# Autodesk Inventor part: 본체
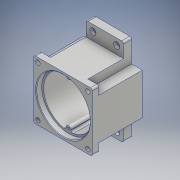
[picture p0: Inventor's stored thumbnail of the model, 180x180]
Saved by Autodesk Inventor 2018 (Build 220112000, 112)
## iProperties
Created: 2020-07
Part Number: 본체
Material: 알루미늄 6061
Document SubType Name: Modeling
Designer: Admin
Density: 2.7 g/cm^3
Appearance: 알루미늄 - 평지
Mass: 876.354 g
Surface Area: 793.925 cm^2
Volume: 324.576 cm^3
Author: Admin
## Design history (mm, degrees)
sketch "스케치1"
  geometry: L1 (65.8, 0)-(-65.8, 0) reference; L2 (0, -65.8)-(0, 65.8) reference; L3 (47, -47)-(-47, -47); L4 (-47, -47)-(-47, 47); L5 (-47, 47)-(47, 47); L6 (47, 47)-(47, -47); L7 (47, -47)-(-47, 47); L8 (-47, -47)-(47, 47); 1 further point
  constraints: 12 end point, 2 midpoint, 2 parallel, 1 horizontal, 1 perpendicular
  dimensions: "d0" = 94 distance of L4.end L5.end; "d1" = 94 distance of L3.end L4.end
extrude "돌출1" new body sketch "스케치1" distance "d2" = 10; taper "d3" = 0 deg
sketch "스케치2"
  geometry: L1 (-65.8, 0)-(65.8, 0) reference; L2 (0, 65.8)-(0, -65.8) reference; L3 (47, -33)-(-47, -33); L4 (-47, -33)-(-47, 33); L5 (-47, 33)-(47, 33); L6 (47, 33)-(47, -33); L7 (47, -33)-(-47, 33); L8 (-47, -33)-(47, 33); 1 further point
  constraints: 12 end point, 2 midpoint, 2 parallel, 1 horizontal, 1 perpendicular
  dimensions: "d4" = 94 distance of L4.end L5.end; "d5" = 66 distance of L3.end L4.end
extrude "돌출2" join sketch "스케치2" distance "d6" = 57; taper "d7" = 0 deg
sketch "스케치3"
  geometry: L1 (-47, -33)-(47, -33) reference; L2 (47, -33)-(47, 33) reference; L3 (47, 33)-(-47, 33) reference; L4 (-47, 33)-(-47, -33) reference; L5 (-65.8, 0)-(65.8, 0) reference; L6 (0, 98)-(0, -98) reference; L7 (30, -70)-(-30, -70); L8 (-30, -70)-(-30, 70); L9 (-30, 70)-(30, 70); L10 (30, 70)-(30, -70); L11 (30, -70)-(-30, 70); L12 (-30, -70)-(30, 70); L13 (-30, -70)-(30, -70); L14 (-30, 70)-(30, 70); L15 (47, -33)-(47, 33) reference; L16 (47, -33)-(47, 33); L17 (-47, -33)-(-47, 33); L18 (47, -33)-(-47, -33) reference; L19 (-47, -33)-(-30, -33); L20 (-30, -70)-(-30, -33); L21 (-47, 33)-(47, 33) reference; L22 (-47, 33)-(-30, 33); L23 (-30, 33)-(-30, 70); L24 (30, -70)-(30, -33); L25 (30, -33)-(47, -33); L26 (30, 33)-(47, 33); L27 (30, 33)-(30, 70); 1 further point
  constraints: 36 end point, 9 point on line, 7 collinear, 2 midpoint, 2 parallel, 1 horizontal, 1 perpendicular, 1 vertical
  dimensions: "d8" = 60 distance of L8.end L9.end; "d9" = 140 distance of L7.end L8.end
extrude "돌출3" join sketch "스케치3" distance "d10" = 13; taper "d11" = 0 deg
sketch "스케치4"
  geometry: L1 (-47, -33)-(-30, -33) reference; L2 (-30, -33)-(-30, -70) reference; L3 (-30, -70)-(30, -70) reference; L4 (30, -70)-(30, -33) reference; L5 (30, -33)-(47, -33) reference; L6 (47, -33)-(47, 33) reference; L7 (47, 33)-(30, 33) reference; L8 (30, 33)-(30, 70) reference; L9 (30, 70)-(-30, 70) reference; L10 (-30, 70)-(-30, 33) reference; L11 (-30, 33)-(-47, 33) reference; L12 (-47, 33)-(-47, -33) reference; L13 (-65.8, 0)-(65.8, 0) reference; L14 (0, 98)-(0, -98) reference; C1 r 27.5 at (-11, 0); 1 further point
  constraints: 1 centre point, 1 point on line
  dimensions: "d12" = 55 diameter of C1; "d13" = 11 distance of point (0, 0) C1.centre
extrude "돌출4" join sketch "스케치4" distance "d14" = 7; taper "d15" = 0 deg
sketch "스케치5"
  geometry: C1 r 27.5 at (0, 0) reference; C2 r 16 at (0, 0); 1 further point
  constraints: 1 centre point, 1 coincident
  dimensions: "d16" = 32 diameter of C2
extrude "돌출5" cut sketch "스케치5" distance "d17" = 8.3; taper "d18" = 0 deg
sketch "스케치6"
  geometry: C1 r 16 at (0, 0) reference; C2 r 12.5 at (0, 0); 1 further point
  constraints: 1 centre point, 1 coincident
  dimensions: "d19" = 25 diameter of C2
extrude "돌출6" cut sketch "스케치6" distance "d20" = 4.7; taper "d21" = 0 deg
sketch "스케치7"
  geometry: C1 r 12.5 at (0, 0) reference; C2 r 17.5 at (0, 0); 1 further point
  constraints: 1 centre point, 1 coincident
  dimensions: "d22" = 35 diameter of C2
extrude "돌출7" cut sketch "스케치7" distance "d23" = 10; taper "d24" = 0 deg
sketch "스케치8"
  geometry: L1 (-47, -47)-(47, -47) reference; L2 (47, -47)-(47, 47) reference; L3 (47, 47)-(-47, 47) reference; L4 (-47, 47)-(-47, -47) reference; L5 (-65.8, 0)-(65.8, 0) reference; L6 (0, -98)-(0, 98) reference; C1 r 43 at (0, 0); 1 further point
  constraints: 1 centre point, 1 coincident
  dimensions: "d25" = 86 diameter of C1
extrude "돌출8" cut sketch "스케치8" distance "d26" = 9; taper "d27" = 0 deg
sketch "스케치9"
  geometry: L1 (-65.8, 0)-(65.8, 0) reference; L2 (0, -98)-(0, 98) reference; C1 r 43 at (0, 0) reference; C2 r 40 at (0, 0); 1 further point
  constraints: 1 centre point, 1 coincident
  dimensions: "d28" = 80 diameter of C2
sketch "스케치10"
  geometry: L1 (-47, 47)-(47, 47) reference; L2 (-47, -47)-(-47, 47) reference; L3 (47, 47)-(47, -47) reference; L4 (47, -47)-(-47, -47) reference; L5 (-65.8, 0)-(65.8, 0) reference; L6 (0, 98)-(0, -98) reference; L7 (-30, 47)-(30, 47); L8 (-30, 47)-(-30, 33); L9 (-30, 33)-(30, 33); L10 (30, 33)-(30, 47); L11 (-30, -47)-(-30, -33); L12 (-30, -33)-(30, -33); L13 (-30, -47)-(30, -47); L14 (30, -33)-(30, -47); 1 further point
  constraints: 16 end point, 5 symmetric about line, 3 perpendicular, 2 point on line
  dimensions: "d29" = 60 distance of L7.start L7.end; "d30" = 14 distance of L7.start L8.end
extrude "돌출9" join sketch "스케치10" stored distance "d31" = 55; taper "d32" = 0 deg
extrude "돌출10" cut sketch "스케치9" distance "d33" = 55; taper "d34" = 0 deg
sketch "스케치11"
  geometry: L1 (-65.8, 0)-(65.8, 0) reference; L2 (0, -98)-(0, 98) reference; C1 r 17.5 at (-11, 0) reference; C2 r 17.5 at (-11, 0) reference; C3 r 40 at (0, 0); A1 r 21 centre (-11, 0) between (7.984, 8.978) and (7.984, -8.978); A2 r 15 centre (20, 0) between (7.984, 8.978) and (7.984, -8.978); A3 r 21 centre (-11, 0) between (7.984, 8.978) and (7.984, -8.978); A4 r 15 centre (20, 0) between (7.984, -8.978) and (7.984, 8.978); 1 further point
  constraints: 8 point on circle, 5 centre point, 4 coincident, 1 point on line
  dimensions: "d35" = 42 diameter of A1; "d36" = 30 diameter of A2; "d37" = 20 distance from line of A2.centre L2; "d38" = 80 diameter of C3
extrude "돌출11" cut sketch "스케치11" distance "d39" = 7; taper "d40" = 0 deg
sketch "스케치12"
  geometry: L1 (-65.8, 0)-(65.8, 0) reference; L2 (0, -98)-(0, 98) reference; C1 r 17.5 at (-11, 0) reference; C2 r 11 at (20, 0); A1 r 15 centre (20, 0) between (7.984, -8.978) and (7.984, 8.978) reference; A2 r 21 centre (-11, 0) between (7.984, 8.978) and (7.984, -8.978) reference; 1 further point
  constraints: 1 centre point, 1 coincident
  dimensions: "d41" = 22 diameter of C2
extrude "돌출12" cut sketch "스케치12" distance "d42" = 7; taper "d43" = 0 deg
sketch "스케치13"
  geometry: C1 r 11 at (0, 0) reference; C2 r 9.5 at (0, 0); 1 further point
  constraints: 1 centre point, 1 coincident
  dimensions: "d44" = 19 diameter of C2
extrude "돌출13" cut sketch "스케치13" distance "d45" = 3; taper "d46" = 0 deg
sketch "스케치14"
  geometry: L1 (-65.8, 0)-(65.8, 0) reference; L2 (0, -98)-(0, 98) reference; L3 (-3.994, 35.778)-(-3.994, 41.932); L4 (3.994, 35.778)-(3.994, 41.932); L5 (3.994, 41.932)-(-3.994, 41.932); L6 (-3.994, 35.778)-(-3.994, 42.814); L7 (3.994, 35.778)-(3.994, 42.814); L8 (-3.994, -35.778)-(-3.994, -42.814); L9 (3.994, -35.778)-(3.994, -42.814); C1 r 40 at (0, 0) reference; A1 r 43 centre (0, 0) between (-3.994, 42.814) and (3.994, 42.814) reference; A2 r 36 centre (0, 0) between (0, 36) and (-3.994, 35.778); A3 r 4 centre (0, 36) between (-3.994, 35.778) and (3.994, 35.778); A4 r 4 centre (0, 36) between (-3.994, 35.778) and (3.994, 35.778); A5 r 43 centre (0, 0) between (3.994, 42.814) and (-3.994, 42.814); A6 r 43 centre (0, 0) between (-3.994, -42.814) and (3.994, -42.814); A7 r 4 centre (0, -36) between (3.994, -35.778) and (-3.994, -35.778); 1 further point
  constraints: 15 point on circle, 14 end point, 6 centre point, 5 symmetric about line, 3 coincident, 3 point on line, 2 vertical, 1 perpendicular, 2 other
  dimensions: "d47" = 72 diameter of A2; "d48" = 8 diameter of A3
extrude "돌출14" join sketch "스케치14" stored distance "d49" = 3; taper "d50" = 0 deg
sketch "스케치15"
  geometry: L1 (-47, -47)-(47, -47) reference; L2 (47, -47)-(47, 47) reference; L3 (47, 47)-(-47, 47) reference; L4 (-47, 47)-(-47, -47) reference; L5 (-65.8, 0)-(65.8, 0) reference; L6 (0, -98)-(0, 98) reference; L7 (40, -40)-(-40, -40); L8 (-40, -40)-(-40, 40); L9 (-40, 40)-(40, 40); L10 (40, 40)-(40, -40); L11 (40, -40)-(-40, 40); L12 (-40, -40)-(40, 40); C1 r 43 at (0, 0) reference; 5 further points
  constraints: 12 end point, 4 coincident, 2 midpoint, 2 parallel, 1 horizontal, 1 perpendicular
  dimensions: "d51" = 80 distance of L8.end L9.end; "d52" = 80 distance of L7.end L8.end
hole "구멍1" sketch "스케치15" at (-40, -40), (-40, 40), (40, 40), (40, -40) diameter "d53" = 7; stored, may be unused: countersink angle "d57" = 90 deg, drill point angle "d59" = 118 deg; dims "d54" = 6, "d55" = 4, "d56" = 2, "d58" = 10
sketch "스케치16"
  geometry: L1 (-65.8, 0)-(65.8, 0) reference; L2 (0, -98)-(0, 98) reference; L3 (19, -60)-(-19, -60); L4 (-19, -60)-(-19, 60); L5 (-19, 60)-(19, 60); L6 (19, 60)-(19, -60); L7 (19, -60)-(-19, 60); L8 (-19, -60)-(19, 60); 5 further points
  constraints: 12 end point, 4 coincident, 2 midpoint, 2 parallel, 1 horizontal, 1 perpendicular
  dimensions: "d60" = 38 distance of L4.end L5.end; "d61" = 120 distance of L3.end L4.end
hole "구멍2" sketch "스케치16" at (-19, 60), (19, 60), (-19, -60), (19, -60) diameter "d62" = 4.5; stored, may be unused: countersink angle "d66" = 90 deg, drill point angle "d68" = 118 deg; dims "d63" = 6, "d64" = 10, "d65" = 5, "d67" = 13
sketch "스케치17"
  geometry: L1 (94, 0)-(0, 0) reference; L2 (94, 0)-(94, 10) reference; L3 (80, 10)-(94, 10) reference; L4 (80, 10)-(80, 80) reference; L5 (14, 80)-(80, 80) reference; L6 (14, 10)-(14, 80) reference; L7 (0, 10)-(14, 10) reference; L8 (0, 0)-(0, 10) reference; L9 (47, -17.4)-(47, 104.4) reference; L10 (-51, 0)-(145, 0) reference; 2 further points
  constraints: 1 other
  dimensions: "d69" = 40 distance from line of L1 point (47, 40)
feature "엠보싱1" sketch "스케치17" dims "d70" = 0.5, "d71" = 0
sketch "스케치18"
  geometry: L1 (3.994, -39.8)-(3.994, -35.778) reference; L2 (-3.994, -35.778)-(-3.994, -39.8) reference; L3 (-3.994, 39.8)-(-3.994, 35.778) reference; L4 (3.994, 35.778)-(3.994, 39.8) reference; C1 r 43 at (0, 0) reference; A1 r 40 centre (0, 0) between (3.994, -39.8) and (3.994, 39.8) reference; A2 r 4 centre (0, -36) between (3.994, -35.778) and (-3.994, -35.778) reference; A3 r 40 centre (0, 0) between (-3.994, 39.8) and (-3.994, -39.8) reference; A4 r 4 centre (0, 36) between (-3.994, 35.778) and (3.994, 35.778) reference; 3 further points
  constraints: 2 coincident
hole "구멍3" sketch "스케치18" at (0, -36), (0, 36) diameter "d72" = 3.242; stored, may be unused: countersink angle "d76" = 90 deg, drill point angle "d78" = 118 deg; dims "d73" = 7, "d74" = 10, "d75" = 5, "d77" = 9
chamfer "모따기1" distance "d79" = 0.8; stored, may be unused: second distance "d80" = 2, angle "d81" = 30 deg
chamfer "모따기2" distance "d82" = 1; stored, may be unused: second distance "d83" = 2, angle "d84" = 45 deg
chamfer "모따기3" distance "d85" = 1; stored, may be unused: second distance "d86" = 2, angle "d87" = 45 deg
fillet "모깎기1" dims "d88" = 3
node "솔리드1"
node "투영된 루프1"
node "투영된 루프2"
node "투영된 루프3"
node "투영된 루프4"
node "투영된 루프5"
node "투영된 루프6"
node "투영된 루프7"
node "투영된 루프8"
node "투영된 루프9"
node "투영된 루프10"
node "투영된 루프11"
node "투영된 루프12"
